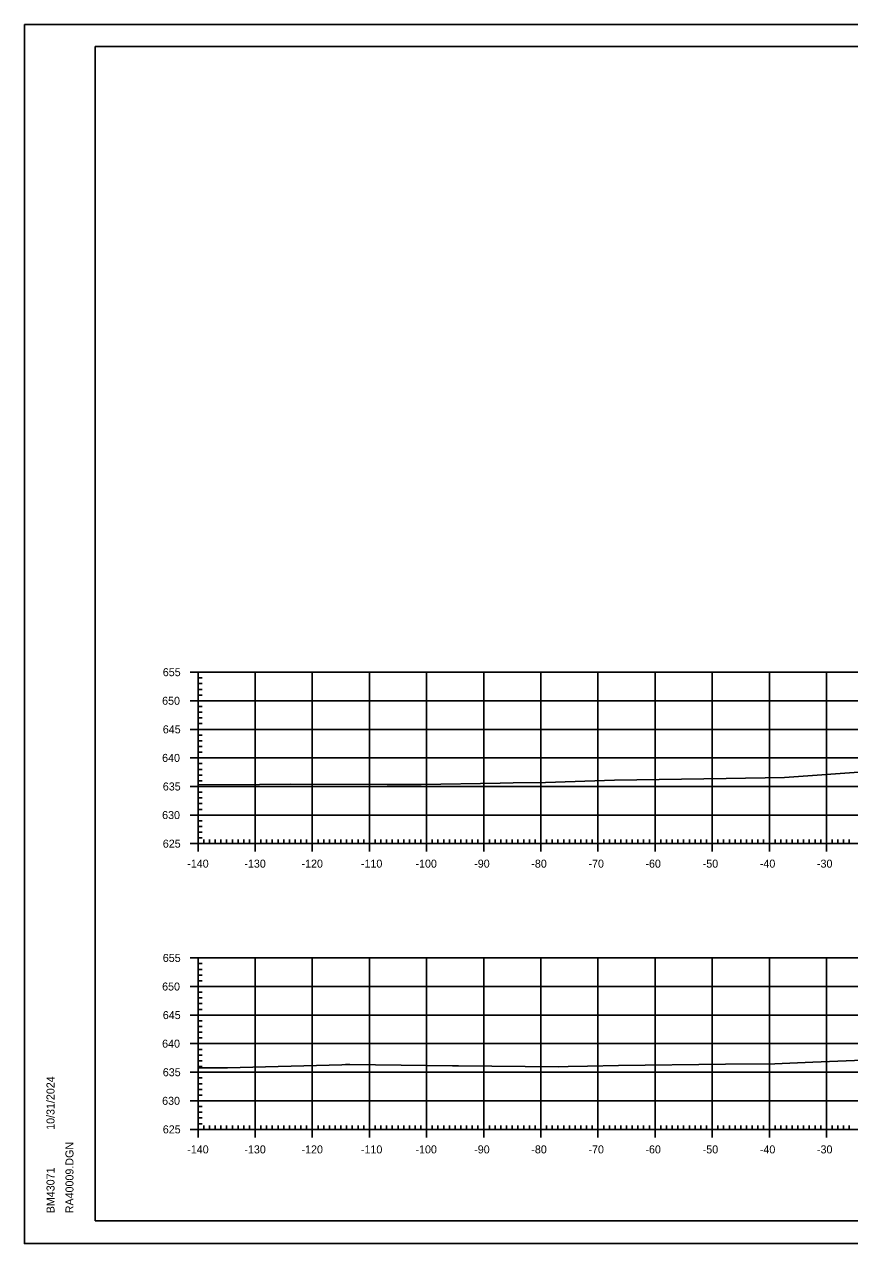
# Model space of a CAD drawing. Extents: x 1381471 to 1382703, y 370300 to 371487.
# Drawn here: x 1381966.2 to 1382110.7, y 371273.8 to 371487.2 of the extents above; entities that cross this region are included whole.
import ezdxf

# ---------------------------------------------------------------- set-up
doc = ezdxf.new("R2010")
doc.units = 0
doc.layers.add('Level 45', color=7, linetype='Continuous')

msp = doc.modelspace()

# ---------------------------------------------------------------- linework, layer by layer
at = {"layer": 'Level 45'}
for p, q in [((1381966.21, 371487.15), (1382299.55, 371487.15)), ((1381978.61, 371483.26), (1382294.79, 371483.26)), ((1381978.61, 371277.8), (1381978.61, 371483.26)), ((1381995.21, 371373.8), (1381998.01, 371373.8)), ((1381996.61, 371373.8), (1382276.61, 371373.8)), ((1381996.61, 371343.8), (1381996.61, 371373.8)), ((1381996.61, 371343.8), (1381996.61, 371373.8)), ((1381996.61, 371372.8), (1381997.31, 371372.8)), ((1381996.61, 371371.8), (1381997.31, 371371.8)), ((1382006.61, 371343.8), (1382006.61, 371373.8)), ((1382016.61, 371343.8), (1382016.61, 371373.8)), ((1382026.61, 371343.8), (1382026.61, 371373.8)), ((1382036.61, 371343.8), (1382036.61, 371373.8)), ((1382046.61, 371343.8), (1382046.61, 371373.8)), ((1382056.61, 371343.8), (1382056.61, 371373.8)), ((1382066.61, 371343.8), (1382066.61, 371373.8)), ((1382076.61, 371343.8), (1382076.61, 371373.8)), ((1382086.61, 371343.8), (1382086.61, 371373.8)), ((1382096.61, 371343.8), (1382096.61, 371373.8)), ((1382106.61, 371343.8), (1382106.61, 371373.8)), ((1381996.61, 371370.8), (1381997.31, 371370.8)), ((1381996.61, 371369.8), (1381997.31, 371369.8)), ((1381995.21, 371368.8), (1381998.01, 371368.8)), ((1381996.61, 371368.8), (1382276.61, 371368.8)), ((1381996.61, 371367.8), (1381997.31, 371367.8)), ((1381996.61, 371366.8), (1381997.31, 371366.8)), ((1381996.61, 371365.8), (1381997.31, 371365.8)), ((1381995.21, 371363.8), (1381998.01, 371363.8)), ((1381996.61, 371364.8), (1381997.31, 371364.8)), ((1381996.61, 371363.8), (1382276.61, 371363.8)), ((1381996.61, 371362.8), (1381997.31, 371362.8)), ((1381996.61, 371361.8), (1381997.31, 371361.8)), ((1381996.61, 371360.8), (1381997.31, 371360.8)), ((1381996.61, 371359.8), (1381997.31, 371359.8)), ((1381995.21, 371358.8), (1381998.01, 371358.8)), ((1381996.61, 371358.8), (1382276.61, 371358.8)), ((1381996.61, 371357.8), (1381997.31, 371357.8)), ((1381996.61, 371356.8), (1381997.31, 371356.8)), ((1381996.61, 371355.8), (1381997.31, 371355.8)), ((1381996.61, 371354.8), (1381997.31, 371354.8)), ((1381995.21, 371353.8), (1381998.01, 371353.8)), ((1381996.61, 371353.8), (1382276.61, 371353.8)), ((1381996.61, 371352.8), (1381997.31, 371352.8)), ((1381996.61, 371351.8), (1381997.31, 371351.8)), ((1381996.61, 371350.8), (1381997.31, 371350.8)), ((1381995.21, 371348.8), (1381998.01, 371348.8)), ((1381996.61, 371349.8), (1381997.31, 371349.8)), ((1381996.61, 371348.8), (1382276.61, 371348.8)), ((1381996.61, 371347.8), (1381997.31, 371347.8)), ((1381996.61, 371346.8), (1381997.31, 371346.8)), ((1381996.61, 371345.8), (1381997.31, 371345.8)), ((1381996.61, 371342.4), (1381996.61, 371345.2)), ((1381996.61, 371344.8), (1381997.31, 371344.8)), ((1381997.61, 371343.8), (1381997.61, 371344.5)), ((1381998.61, 371343.8), (1381998.61, 371344.5)), ((1381999.61, 371343.8), (1381999.61, 371344.5)), ((1382000.61, 371343.8), (1382000.61, 371344.5)), ((1382001.61, 371343.8), (1382001.61, 371344.5)), ((1382002.61, 371343.8), (1382002.61, 371344.5)), ((1382003.61, 371343.8), (1382003.61, 371344.5)), ((1382004.61, 371343.8), (1382004.61, 371344.5)), ((1382005.61, 371343.8), (1382005.61, 371344.5)), ((1382006.61, 371342.4), (1382006.61, 371345.2)), ((1382007.61, 371343.8), (1382007.61, 371344.5)), ((1382008.61, 371343.8), (1382008.61, 371344.5)), ((1382009.61, 371343.8), (1382009.61, 371344.5)), ((1382010.61, 371343.8), (1382010.61, 371344.5)), ((1382011.61, 371343.8), (1382011.61, 371344.5)), ((1382012.61, 371343.8), (1382012.61, 371344.5)), ((1382013.61, 371343.8), (1382013.61, 371344.5)), ((1382014.61, 371343.8), (1382014.61, 371344.5)), ((1382015.61, 371343.8), (1382015.61, 371344.5)), ((1382016.61, 371342.4), (1382016.61, 371345.2)), ((1382017.61, 371343.8), (1382017.61, 371344.5)), ((1382018.61, 371343.8), (1382018.61, 371344.5)), ((1382019.61, 371343.8), (1382019.61, 371344.5)), ((1382020.61, 371343.8), (1382020.61, 371344.5)), ((1382021.61, 371343.8), (1382021.61, 371344.5)), ((1382022.61, 371343.8), (1382022.61, 371344.5)), ((1382023.61, 371343.8), (1382023.61, 371344.5)), ((1382024.61, 371343.8), (1382024.61, 371344.5)), ((1382025.61, 371343.8), (1382025.61, 371344.5)), ((1382026.61, 371342.4), (1382026.61, 371345.2)), ((1382027.61, 371343.8), (1382027.61, 371344.5)), ((1382028.61, 371343.8), (1382028.61, 371344.5)), ((1382029.61, 371343.8), (1382029.61, 371344.5)), ((1382030.61, 371343.8), (1382030.61, 371344.5)), ((1382031.61, 371343.8), (1382031.61, 371344.5)), ((1382032.61, 371343.8), (1382032.61, 371344.5)), ((1382033.61, 371343.8), (1382033.61, 371344.5)), ((1382034.61, 371343.8), (1382034.61, 371344.5)), ((1382035.61, 371343.8), (1382035.61, 371344.5)), ((1382036.61, 371342.4), (1382036.61, 371345.2)), ((1382037.61, 371343.8), (1382037.61, 371344.5)), ((1382038.61, 371343.8), (1382038.61, 371344.5)), ((1382039.61, 371343.8), (1382039.61, 371344.5)), ((1382040.61, 371343.8), (1382040.61, 371344.5)), ((1382041.61, 371343.8), (1382041.61, 371344.5)), ((1382042.61, 371343.8), (1382042.61, 371344.5)), ((1382043.61, 371343.8), (1382043.61, 371344.5)), ((1382044.61, 371343.8), (1382044.61, 371344.5)), ((1382045.61, 371343.8), (1382045.61, 371344.5)), ((1382046.61, 371342.4), (1382046.61, 371345.2)), ((1382047.61, 371343.8), (1382047.61, 371344.5)), ((1382048.61, 371343.8), (1382048.61, 371344.5)), ((1382049.61, 371343.8), (1382049.61, 371344.5)), ((1382050.61, 371343.8), (1382050.61, 371344.5)), ((1382051.61, 371343.8), (1382051.61, 371344.5)), ((1382052.61, 371343.8), (1382052.61, 371344.5)), ((1382053.61, 371343.8), (1382053.61, 371344.5)), ((1382054.61, 371343.8), (1382054.61, 371344.5)), ((1382055.61, 371343.8), (1382055.61, 371344.5)), ((1382056.61, 371342.4), (1382056.61, 371345.2)), ((1382057.61, 371343.8), (1382057.61, 371344.5)), ((1382058.61, 371343.8), (1382058.61, 371344.5)), ((1382059.61, 371343.8), (1382059.61, 371344.5)), ((1382060.61, 371343.8), (1382060.61, 371344.5)), ((1382061.61, 371343.8), (1382061.61, 371344.5)), ((1382062.61, 371343.8), (1382062.61, 371344.5)), ((1382063.61, 371343.8), (1382063.61, 371344.5)), ((1382064.61, 371343.8), (1382064.61, 371344.5)), ((1382065.61, 371343.8), (1382065.61, 371344.5)), ((1382066.61, 371342.4), (1382066.61, 371345.2)), ((1382067.61, 371343.8), (1382067.61, 371344.5)), ((1382068.61, 371343.8), (1382068.61, 371344.5)), ((1382069.61, 371343.8), (1382069.61, 371344.5)), ((1382070.61, 371343.8), (1382070.61, 371344.5)), ((1382071.61, 371343.8), (1382071.61, 371344.5)), ((1382072.61, 371343.8), (1382072.61, 371344.5)), ((1382073.61, 371343.8), (1382073.61, 371344.5)), ((1382074.61, 371343.8), (1382074.61, 371344.5)), ((1382075.61, 371343.8), (1382075.61, 371344.5)), ((1382076.61, 371342.4), (1382076.61, 371345.2)), ((1382077.61, 371343.8), (1382077.61, 371344.5)), ((1382078.61, 371343.8), (1382078.61, 371344.5)), ((1382079.61, 371343.8), (1382079.61, 371344.5)), ((1382080.61, 371343.8), (1382080.61, 371344.5)), ((1382081.61, 371343.8), (1382081.61, 371344.5)), ((1382082.61, 371343.8), (1382082.61, 371344.5)), ((1382083.61, 371343.8), (1382083.61, 371344.5)), ((1382084.61, 371343.8), (1382084.61, 371344.5)), ((1382085.61, 371343.8), (1382085.61, 371344.5)), ((1382086.61, 371342.4), (1382086.61, 371345.2)), ((1382087.61, 371343.8), (1382087.61, 371344.5)), ((1382088.61, 371343.8), (1382088.61, 371344.5)), ((1382089.61, 371343.8), (1382089.61, 371344.5)), ((1382090.61, 371343.8), (1382090.61, 371344.5)), ((1382091.61, 371343.8), (1382091.61, 371344.5)), ((1382092.61, 371343.8), (1382092.61, 371344.5)), ((1382093.61, 371343.8), (1382093.61, 371344.5)), ((1382094.61, 371343.8), (1382094.61, 371344.5)), ((1382095.61, 371343.8), (1382095.61, 371344.5)), ((1382096.61, 371342.4), (1382096.61, 371345.2)), ((1382097.61, 371343.8), (1382097.61, 371344.5)), ((1382098.61, 371343.8), (1382098.61, 371344.5)), ((1382099.61, 371343.8), (1382099.61, 371344.5)), ((1382100.61, 371343.8), (1382100.61, 371344.5)), ((1382101.61, 371343.8), (1382101.61, 371344.5)), ((1382102.61, 371343.8), (1382102.61, 371344.5)), ((1382103.61, 371343.8), (1382103.61, 371344.5)), ((1382104.61, 371343.8), (1382104.61, 371344.5)), ((1382105.61, 371343.8), (1382105.61, 371344.5)), ((1382106.61, 371342.4), (1382106.61, 371345.2)), ((1382107.61, 371343.8), (1382107.61, 371344.5)), ((1382108.61, 371343.8), (1382108.61, 371344.5)), ((1382109.61, 371343.8), (1382109.61, 371344.5)), ((1382110.61, 371343.8), (1382110.61, 371344.5)), ((1381995.21, 371343.8), (1381998.01, 371343.8)), ((1381996.61, 371343.8), (1382276.61, 371343.8)), ((1381996.61, 371343.8), (1382276.61, 371343.8)), ((1381995.21, 371323.8), (1381998.01, 371323.8)), ((1381996.61, 371323.8), (1382276.61, 371323.8)), ((1381996.61, 371293.8), (1381996.61, 371323.8)), ((1381996.61, 371293.8), (1381996.61, 371323.8)), ((1381996.61, 371322.8), (1381997.31, 371322.8)), ((1382006.61, 371293.8), (1382006.61, 371323.8)), ((1382016.61, 371293.8), (1382016.61, 371323.8)), ((1382026.61, 371293.8), (1382026.61, 371323.8)), ((1382036.61, 371293.8), (1382036.61, 371323.8)), ((1382046.61, 371293.8), (1382046.61, 371323.8)), ((1382056.61, 371293.8), (1382056.61, 371323.8)), ((1382066.61, 371293.8), (1382066.61, 371323.8)), ((1382076.61, 371293.8), (1382076.61, 371323.8)), ((1382086.61, 371293.8), (1382086.61, 371323.8)), ((1382096.61, 371293.8), (1382096.61, 371323.8)), ((1382106.61, 371293.8), (1382106.61, 371323.8)), ((1381996.61, 371321.8), (1381997.31, 371321.8)), ((1381996.61, 371320.8), (1381997.31, 371320.8)), ((1381995.21, 371318.8), (1381998.01, 371318.8)), ((1381996.61, 371319.8), (1381997.31, 371319.8)), ((1381996.61, 371318.8), (1382276.61, 371318.8)), ((1381996.61, 371317.8), (1381997.31, 371317.8)), ((1381996.61, 371316.8), (1381997.31, 371316.8)), ((1381996.61, 371315.8), (1381997.31, 371315.8)), ((1381996.61, 371314.8), (1381997.31, 371314.8)), ((1381995.21, 371313.8), (1381998.01, 371313.8)), ((1381996.61, 371313.8), (1382276.61, 371313.8)), ((1381996.61, 371312.8), (1381997.31, 371312.8)), ((1381996.61, 371311.8), (1381997.31, 371311.8)), ((1381996.61, 371310.8), (1381997.31, 371310.8)), ((1381995.21, 371308.8), (1381998.01, 371308.8)), ((1381996.61, 371309.8), (1381997.31, 371309.8)), ((1381996.61, 371308.8), (1382276.61, 371308.8)), ((1381996.61, 371307.8), (1381997.31, 371307.8)), ((1381996.61, 371306.8), (1381997.31, 371306.8)), ((1381996.61, 371305.8), (1381997.31, 371305.8)), ((1381995.21, 371303.8), (1381998.01, 371303.8)), ((1381996.61, 371304.8), (1381997.31, 371304.8)), ((1381996.61, 371303.8), (1382276.61, 371303.8)), ((1381996.61, 371302.8), (1381997.31, 371302.8)), ((1381996.61, 371301.8), (1381997.31, 371301.8)), ((1381996.61, 371300.8), (1381997.31, 371300.8)), ((1381996.61, 371299.8), (1381997.31, 371299.8)), ((1381995.21, 371298.8), (1381998.01, 371298.8)), ((1381996.61, 371298.8), (1382276.61, 371298.8)), ((1381996.61, 371297.8), (1381997.31, 371297.8)), ((1381996.61, 371296.8), (1381997.31, 371296.8)), ((1381996.61, 371295.8), (1381997.31, 371295.8)), ((1381996.61, 371292.4), (1381996.61, 371295.2)), ((1382006.61, 371292.4), (1382006.61, 371295.2)), ((1382016.61, 371292.4), (1382016.61, 371295.2)), ((1382026.61, 371292.4), (1382026.61, 371295.2)), ((1382036.61, 371292.4), (1382036.61, 371295.2)), ((1382046.61, 371292.4), (1382046.61, 371295.2)), ((1382056.61, 371292.4), (1382056.61, 371295.2)), ((1382066.61, 371292.4), (1382066.61, 371295.2)), ((1382076.61, 371292.4), (1382076.61, 371295.2)), ((1382086.61, 371292.4), (1382086.61, 371295.2)), ((1382096.61, 371292.4), (1382096.61, 371295.2)), ((1382106.61, 371292.4), (1382106.61, 371295.2)), ((1381995.21, 371293.8), (1381998.01, 371293.8)), ((1381996.61, 371294.8), (1381997.31, 371294.8)), ((1381996.61, 371293.8), (1382276.61, 371293.8)), ((1381996.61, 371293.8), (1382276.61, 371293.8)), ((1381997.61, 371293.8), (1381997.61, 371294.5)), ((1381998.61, 371293.8), (1381998.61, 371294.5)), ((1381999.61, 371293.8), (1381999.61, 371294.5)), ((1382000.61, 371293.8), (1382000.61, 371294.5)), ((1382001.61, 371293.8), (1382001.61, 371294.5)), ((1382002.61, 371293.8), (1382002.61, 371294.5)), ((1382003.61, 371293.8), (1382003.61, 371294.5)), ((1382004.61, 371293.8), (1382004.61, 371294.5)), ((1382005.61, 371293.8), (1382005.61, 371294.5)), ((1382007.61, 371293.8), (1382007.61, 371294.5)), ((1382008.61, 371293.8), (1382008.61, 371294.5)), ((1382009.61, 371293.8), (1382009.61, 371294.5)), ((1382010.61, 371293.8), (1382010.61, 371294.5)), ((1382011.61, 371293.8), (1382011.61, 371294.5)), ((1382012.61, 371293.8), (1382012.61, 371294.5)), ((1382013.61, 371293.8), (1382013.61, 371294.5)), ((1382014.61, 371293.8), (1382014.61, 371294.5)), ((1382015.61, 371293.8), (1382015.61, 371294.5)), ((1382017.61, 371293.8), (1382017.61, 371294.5)), ((1382018.61, 371293.8), (1382018.61, 371294.5)), ((1382019.61, 371293.8), (1382019.61, 371294.5)), ((1382020.61, 371293.8), (1382020.61, 371294.5)), ((1382021.61, 371293.8), (1382021.61, 371294.5)), ((1382022.61, 371293.8), (1382022.61, 371294.5)), ((1382023.61, 371293.8), (1382023.61, 371294.5)), ((1382024.61, 371293.8), (1382024.61, 371294.5)), ((1382025.61, 371293.8), (1382025.61, 371294.5)), ((1382027.61, 371293.8), (1382027.61, 371294.5)), ((1382028.61, 371293.8), (1382028.61, 371294.5)), ((1382029.61, 371293.8), (1382029.61, 371294.5)), ((1382030.61, 371293.8), (1382030.61, 371294.5)), ((1382031.61, 371293.8), (1382031.61, 371294.5)), ((1382032.61, 371293.8), (1382032.61, 371294.5)), ((1382033.61, 371293.8), (1382033.61, 371294.5)), ((1382034.61, 371293.8), (1382034.61, 371294.5)), ((1382035.61, 371293.8), (1382035.61, 371294.5)), ((1382037.61, 371293.8), (1382037.61, 371294.5)), ((1382038.61, 371293.8), (1382038.61, 371294.5)), ((1382039.61, 371293.8), (1382039.61, 371294.5)), ((1382040.61, 371293.8), (1382040.61, 371294.5)), ((1382041.61, 371293.8), (1382041.61, 371294.5)), ((1382042.61, 371293.8), (1382042.61, 371294.5)), ((1382043.61, 371293.8), (1382043.61, 371294.5)), ((1382044.61, 371293.8), (1382044.61, 371294.5)), ((1382045.61, 371293.8), (1382045.61, 371294.5)), ((1382047.61, 371293.8), (1382047.61, 371294.5)), ((1382048.61, 371293.8), (1382048.61, 371294.5)), ((1382049.61, 371293.8), (1382049.61, 371294.5)), ((1382050.61, 371293.8), (1382050.61, 371294.5)), ((1382051.61, 371293.8), (1382051.61, 371294.5)), ((1382052.61, 371293.8), (1382052.61, 371294.5)), ((1382053.61, 371293.8), (1382053.61, 371294.5)), ((1382054.61, 371293.8), (1382054.61, 371294.5)), ((1382055.61, 371293.8), (1382055.61, 371294.5)), ((1382057.61, 371293.8), (1382057.61, 371294.5)), ((1382058.61, 371293.8), (1382058.61, 371294.5)), ((1382059.61, 371293.8), (1382059.61, 371294.5)), ((1382060.61, 371293.8), (1382060.61, 371294.5)), ((1382061.61, 371293.8), (1382061.61, 371294.5)), ((1382062.61, 371293.8), (1382062.61, 371294.5)), ((1382063.61, 371293.8), (1382063.61, 371294.5)), ((1382064.61, 371293.8), (1382064.61, 371294.5)), ((1382065.61, 371293.8), (1382065.61, 371294.5)), ((1382067.61, 371293.8), (1382067.61, 371294.5)), ((1382068.61, 371293.8), (1382068.61, 371294.5)), ((1382069.61, 371293.8), (1382069.61, 371294.5)), ((1382070.61, 371293.8), (1382070.61, 371294.5)), ((1382071.61, 371293.8), (1382071.61, 371294.5)), ((1382072.61, 371293.8), (1382072.61, 371294.5)), ((1382073.61, 371293.8), (1382073.61, 371294.5)), ((1382074.61, 371293.8), (1382074.61, 371294.5)), ((1382075.61, 371293.8), (1382075.61, 371294.5)), ((1382077.61, 371293.8), (1382077.61, 371294.5)), ((1382078.61, 371293.8), (1382078.61, 371294.5)), ((1382079.61, 371293.8), (1382079.61, 371294.5)), ((1382080.61, 371293.8), (1382080.61, 371294.5)), ((1382081.61, 371293.8), (1382081.61, 371294.5)), ((1382082.61, 371293.8), (1382082.61, 371294.5)), ((1382083.61, 371293.8), (1382083.61, 371294.5)), ((1382084.61, 371293.8), (1382084.61, 371294.5)), ((1382085.61, 371293.8), (1382085.61, 371294.5)), ((1382087.61, 371293.8), (1382087.61, 371294.5)), ((1382088.61, 371293.8), (1382088.61, 371294.5)), ((1382089.61, 371293.8), (1382089.61, 371294.5)), ((1382090.61, 371293.8), (1382090.61, 371294.5)), ((1382091.61, 371293.8), (1382091.61, 371294.5)), ((1382092.61, 371293.8), (1382092.61, 371294.5)), ((1382093.61, 371293.8), (1382093.61, 371294.5)), ((1382094.61, 371293.8), (1382094.61, 371294.5)), ((1382095.61, 371293.8), (1382095.61, 371294.5)), ((1382097.61, 371293.8), (1382097.61, 371294.5)), ((1382098.61, 371293.8), (1382098.61, 371294.5)), ((1382099.61, 371293.8), (1382099.61, 371294.5)), ((1382100.61, 371293.8), (1382100.61, 371294.5)), ((1382101.61, 371293.8), (1382101.61, 371294.5)), ((1382102.61, 371293.8), (1382102.61, 371294.5)), ((1382103.61, 371293.8), (1382103.61, 371294.5)), ((1382104.61, 371293.8), (1382104.61, 371294.5)), ((1382105.61, 371293.8), (1382105.61, 371294.5)), ((1382107.61, 371293.8), (1382107.61, 371294.5)), ((1382108.61, 371293.8), (1382108.61, 371294.5)), ((1382109.61, 371293.8), (1382109.61, 371294.5)), ((1382110.61, 371293.8), (1382110.61, 371294.5)), ((1381978.61, 371277.8), (1381978.61, 371277.8)), ((1382294.79, 371277.8), (1381978.61, 371277.8)), ((1381966.21, 371273.82), (1382299.55, 371273.82))]:
    msp.add_line(p, q, dxfattribs=at)
for points in [[(1381966.21, 371487.15), (1382299.55, 371487.15), (1382299.55, 371273.81), (1381966.21, 371273.81)], [(1382212.53, 371483.26), (1382232.15, 371483.26), (1382232.15, 371473.38), (1382248.27, 371473.38), (1382271.46, 371473.38), (1382271.46, 371449.04), (1382294.79, 371449.04), (1382294.79, 371277.8), (1381978.61, 371277.8), (1381978.61, 371483.26)]]:
    msp.add_lwpolyline(points, close=True, dxfattribs=at)
for points in [[(1381996.61, 371354.11), (1382007.37, 371354.12), (1382012.75, 371354.22), (1382029.71, 371354.17), (1382030.9, 371354.16), (1382035.68, 371354.16), (1382049.49, 371354.38), (1382051.75, 371354.44), (1382057.42, 371354.52), (1382069.52, 371354.9), (1382089.04, 371355.21), (1382099.24, 371355.38), (1382100.9, 371355.48), (1382113.11, 371356.34)], [(1381996.61, 371304.56), (1381999.53, 371304.56), (1382001.79, 371304.58), (1382021.78, 371305.12), (1382022.4, 371305.13), (1382023.19, 371305.14), (1382041.15, 371304.92), (1382042.21, 371304.94), (1382059.73, 371304.74), (1382061.37, 371304.82), (1382064.77, 371304.87), (1382070.18, 371305), (1382088.95, 371305.22), (1382097.6, 371305.3), (1382098.85, 371305.32), (1382104.21, 371305.54), (1382112.95, 371305.94)]]:
    msp.add_lwpolyline(points, dxfattribs=at)

# ---------------------------------------------------------------- texts
for s, p in [('655', (1381990.44, 371373.1)), ('650', (1381990.32, 371368.1)), ('645', (1381990.44, 371363.1)), ('640', (1381990.32, 371358.1)), ('635', (1381990.44, 371353.1)), ('630', (1381990.32, 371348.1)), ('625', (1381990.44, 371343.1)), ('-140', (1381994.72, 371339.6)), ('-130', (1382004.72, 371339.6)), ('-120', (1382014.72, 371339.6)), ('-110', (1382025.12, 371339.6)), ('-100', (1382034.67, 371339.6)), ('-90', (1382044.95, 371339.6)), ('-80', (1382054.95, 371339.6)), ('-70', (1382064.95, 371339.6)), ('-60', (1382074.92, 371339.6)), ('-50', (1382084.95, 371339.6)), ('-40', (1382094.95, 371339.6)), ('-30', (1382104.95, 371339.6)), ('655', (1381990.44, 371323.1)), ('650', (1381990.32, 371318.1)), ('645', (1381990.44, 371313.1)), ('640', (1381990.32, 371308.1)), ('635', (1381990.44, 371303.1)), ('630', (1381990.32, 371298.1)), ('625', (1381990.44, 371293.1)), ('-140', (1381994.72, 371289.6)), ('-130', (1382004.72, 371289.6)), ('-120', (1382014.72, 371289.6)), ('-110', (1382025.12, 371289.6)), ('-100', (1382034.67, 371289.6)), ('-90', (1382044.95, 371289.6)), ('-80', (1382054.95, 371289.6)), ('-70', (1382064.95, 371289.6)), ('-60', (1382074.92, 371289.6)), ('-50', (1382084.95, 371289.6)), ('-40', (1382094.95, 371289.6)), ('-30', (1382104.95, 371289.6))]:
    msp.add_text(s, height=1.4, dxfattribs=at).set_placement(p)
for s, p in [('10/31/2024', (1381971.48, 371293.72)), ('RA40009.DGN', (1381974.8, 371279.12)), ('BM43071', (1381971.48, 371279.12))]:
    msp.add_text(s, height=1.4, rotation=90, dxfattribs=at).set_placement(p)

doc.saveas('drawing.dxf')
